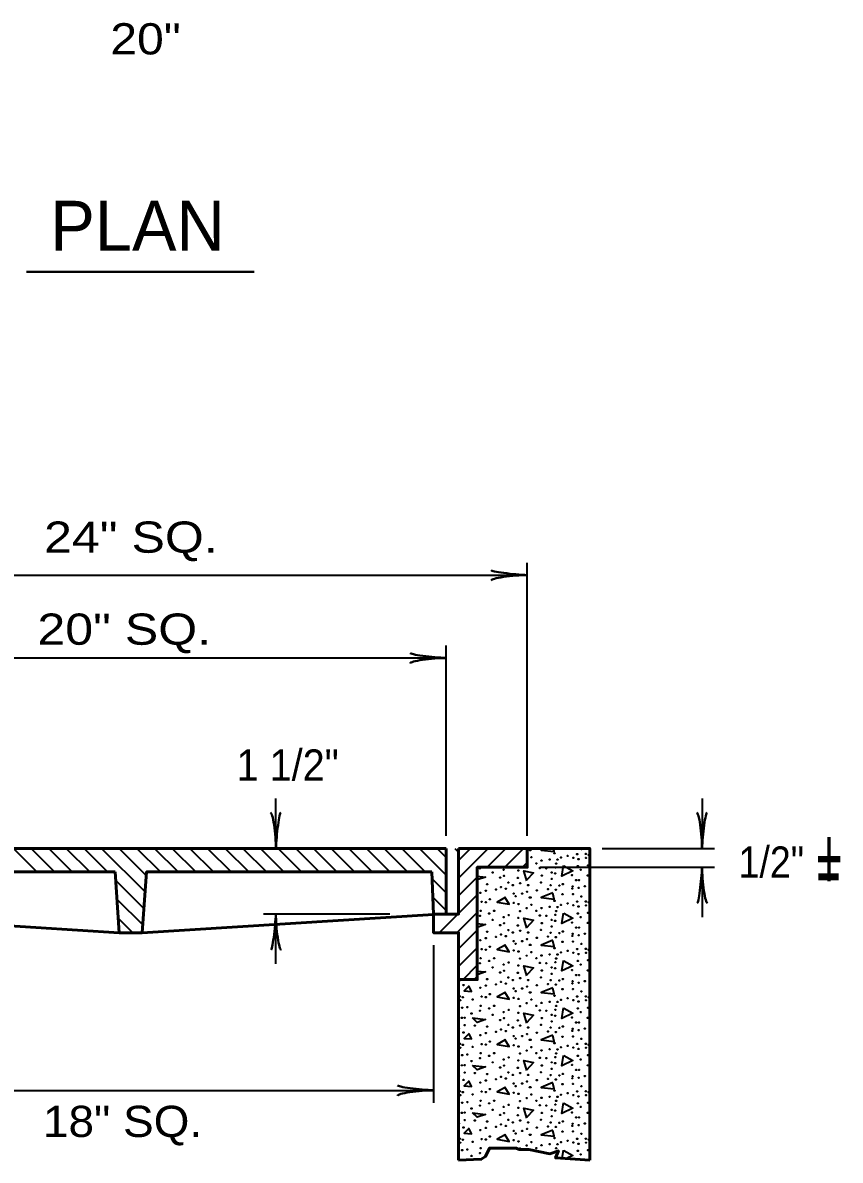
# Model space of a CAD drawing. Extents: x 788 to 1469, y -1 to 439.
# Drawn here: x 1143.7 to 1209.2, y 217.4 to 308.5 of the extents above; entities that cross this region are included whole.
import ezdxf

# ---------------------------------------------------------------- set-up
doc = ezdxf.new("R2010")
doc.units = 0
doc.layers.add('1', color=7, linetype='Continuous', lineweight=35)

msp = doc.modelspace()

# ---------------------------------------------------------------- linework, layer by layer
at = {"layer": '1', "lineweight": 40}
msp.add_line((1144.038, 288.534), (1162.275, 288.534), dxfattribs=at)
at = {"layer": '1'}
for p, q in [((1184.152, 243.348), (1184.152, 265.229)), ((1120.652, 264.229), (1184.152, 264.229)), ((1177.652, 243.348), (1177.652, 258.601)), ((1127.152, 257.601), (1177.652, 257.601)), ((1164.019, 242.348), (1164.019, 246.348)), ((1198.152, 246.348), (1198.152, 242.348)), ((1142.996, 242.348), (1144.871, 240.473)), ((1144.41, 242.348), (1146.285, 240.473)), ((1145.824, 242.348), (1147.699, 240.473)), ((1147.238, 242.348), (1149.113, 240.473)), ((1148.653, 242.348), (1150.528, 240.473)), ((1150.067, 242.348), (1153.55, 238.865)), ((1151.481, 242.348), (1153.641, 240.188)), ((1152.895, 242.348), (1154.77, 240.473)), ((1154.31, 242.348), (1156.185, 240.473)), ((1155.724, 242.348), (1157.599, 240.473)), ((1157.138, 242.348), (1159.013, 240.473)), ((1158.552, 242.348), (1160.427, 240.473)), ((1159.966, 242.348), (1161.841, 240.473)), ((1161.381, 242.348), (1163.256, 240.473)), ((1162.795, 242.348), (1164.67, 240.473)), ((1164.209, 242.348), (1166.084, 240.473)), ((1165.623, 242.348), (1167.498, 240.473)), ((1167.037, 242.348), (1168.912, 240.473)), ((1168.452, 242.348), (1170.327, 240.473)), ((1169.866, 242.348), (1171.741, 240.473)), ((1171.28, 242.348), (1173.155, 240.473)), ((1172.694, 242.348), (1174.569, 240.473)), ((1174.109, 242.348), (1175.984, 240.473)), ((1175.523, 242.348), (1177.652, 240.219)), ((1176.937, 242.348), (1177.652, 241.633)), ((1178.351, 242.348), (1178.652, 242.047)), ((1178.652, 241.388), (1179.612, 242.348)), ((1178.652, 239.973), (1181.026, 242.348)), ((1180.941, 240.848), (1182.441, 242.348)), ((1182.355, 240.848), (1183.855, 242.348)), ((1190.152, 242.348), (1199.152, 242.348)), ((1183.769, 240.848), (1184.152, 241.231)), ((1185.152, 240.848), (1199.152, 240.848)), ((1198.152, 240.848), (1198.152, 236.848)), ((1151.189, 239.812), (1153.458, 237.542)), ((1176.544, 239.913), (1177.652, 238.805)), ((1178.652, 238.559), (1180.152, 240.059)), ((1151.294, 238.293), (1153.367, 236.219)), ((1176.6, 238.442), (1177.652, 237.39)), ((1178.652, 237.145), (1180.152, 238.645)), ((1173.152, 237.098), (1163.019, 237.098)), ((1164.019, 233.098), (1164.019, 237.098)), ((1177.152, 237.059), (1177.191, 237.098)), ((1177.152, 235.645), (1178.605, 237.098)), ((1178.519, 235.598), (1180.152, 237.231)), ((1151.398, 236.774), (1152.574, 235.598)), ((1178.652, 234.317), (1180.152, 235.817)), ((1176.652, 234.598), (1176.652, 221.972)), ((1178.652, 232.902), (1180.152, 234.402)), ((1179.012, 231.848), (1180.152, 232.988)), ((1128.152, 222.972), (1176.652, 222.972)), ((1186.957, 217.531), (1187.049, 218.176))]:
    msp.add_line(p, q, dxfattribs=at)
at = {"layer": '1', "lineweight": 53}
for p, q in [((1127.152, 242.348), (1177.652, 242.348)), ((1177.652, 237.098), (1177.652, 242.348)), ((1178.652, 242.348), (1178.652, 238.598)), ((1151.143, 240.473), (1128.282, 240.473)), ((1176.522, 240.473), (1176.652, 237.079)), ((1128.152, 237.066), (1151.479, 235.598)), ((1153.324, 235.598), (1176.651, 237.066)), ((1180.152, 232.017), (1179.983, 231.848))]:
    msp.add_line(p, q, dxfattribs=at)
msp.add_lwpolyline([(1178.652, 242.348), (1184.152, 242.348), (1184.152, 240.848), (1180.152, 240.848), (1180.152, 231.848), (1178.652, 231.848), (1178.652, 235.598), (1176.651, 235.598), (1176.651, 237.098), (1178.652, 237.098)], close=True, dxfattribs=at)
for points in [[(1189.152, 217.379), (1189.152, 242.348), (1184.152, 242.348), (1184.152, 240.848), (1180.152, 240.848), (1180.152, 231.848), (1178.652, 231.848), (1178.652, 217.379)], [(1176.522, 240.473), (1153.66, 240.473), (1153.324, 235.598), (1151.479, 235.598), (1151.143, 240.473)], [(1178.652, 217.379), (1180.461, 217.456), (1180.799, 217.681), (1181.136, 218.356), (1183.271, 218.356), (1183.496, 218.243), (1184.283, 218.243), (1185.969, 217.906), (1186.643, 218.131), (1186.419, 217.569), (1189.152, 217.379)]]:
    msp.add_lwpolyline(points, dxfattribs=at)
at = {"layer": '1'}
for points in [[(1185.595, 242.348), (1185.269, 242.216), (1186.31, 242.096), (1186.255, 242.348)], [(1184.11, 239.756), (1183.87, 240.556), (1184.649, 240.396), (1184.09, 239.796)], [(1187.09, 240.956), (1187.789, 240.556), (1186.929, 240.136), (1187.049, 240.976)], [(1180.152, 240.132), (1180.81, 240.056), (1180.152, 239.824)], [(1186.209, 238.796), (1185.269, 238.416), (1186.31, 238.296), (1186.209, 238.756)], [(1182.389, 238.416), (1181.729, 238.056), (1182.709, 237.876), (1182.35, 238.436)], [(1187.09, 237.156), (1187.789, 236.756), (1186.929, 236.336), (1187.049, 237.176)], [(1180.152, 236.332), (1180.81, 236.256), (1180.152, 236.024)], [(1184.11, 235.956), (1183.87, 236.756), (1184.649, 236.596), (1184.09, 235.996)], [(1182.389, 234.616), (1181.729, 234.256), (1182.709, 234.076), (1182.35, 234.636)], [(1186.209, 234.996), (1185.269, 234.616), (1186.31, 234.496), (1186.209, 234.956)], [(1187.09, 233.356), (1187.789, 232.956), (1186.929, 232.536), (1187.049, 233.376)], [(1180.152, 232.532), (1180.81, 232.456), (1180.152, 232.224)], [(1184.11, 232.156), (1183.87, 232.956), (1184.649, 232.796), (1184.09, 232.196)], [(1179.489, 231.336), (1179.11, 230.936), (1179.689, 230.896), (1179.489, 231.296)], [(1182.389, 230.816), (1181.729, 230.456), (1182.709, 230.276), (1182.35, 230.836)], [(1186.209, 231.196), (1185.269, 230.816), (1186.31, 230.696), (1186.209, 231.156)], [(1187.09, 229.556), (1187.789, 229.156), (1186.929, 228.736), (1187.049, 229.576)], [(1184.11, 228.356), (1183.87, 229.156), (1184.649, 228.996), (1184.09, 228.396)], [(1179.489, 227.536), (1179.11, 227.136), (1179.689, 227.096), (1179.489, 227.496)], [(1182.389, 227.016), (1181.729, 226.656), (1182.709, 226.476), (1182.35, 227.036)], [(1186.209, 227.396), (1185.269, 227.016), (1186.31, 226.896), (1186.209, 227.356)], [(1184.11, 224.556), (1183.87, 225.356), (1184.649, 225.196), (1184.09, 224.596)], [(1187.09, 225.756), (1187.789, 225.356), (1186.929, 224.936), (1187.049, 225.776)], [(1179.489, 223.736), (1179.11, 223.336), (1179.689, 223.296), (1179.489, 223.696)], [(1182.389, 223.216), (1181.729, 222.856), (1182.709, 222.676), (1182.35, 223.236)], [(1186.209, 223.596), (1185.269, 223.216), (1186.31, 223.096), (1186.209, 223.556)], [(1184.11, 220.756), (1183.87, 221.556), (1184.649, 221.396), (1184.09, 220.796)], [(1187.09, 221.956), (1187.789, 221.556), (1186.929, 221.136), (1187.049, 221.976)], [(1179.489, 219.936), (1179.11, 219.536), (1179.689, 219.496), (1179.489, 219.896)], [(1186.209, 219.796), (1185.269, 219.416), (1186.31, 219.296), (1186.209, 219.756)], [(1182.389, 219.416), (1181.729, 219.056), (1182.709, 218.876), (1182.35, 219.436)], [(1187.09, 218.156), (1187.789, 217.756), (1187.283, 217.509)]]:
    msp.add_lwpolyline(points, dxfattribs=at)
for points in [[(1179.769, 228.776), (1180.81, 228.656), (1180.13, 228.416)], [(1179.769, 224.976), (1180.81, 224.856), (1180.13, 224.616)], [(1179.769, 221.176), (1180.81, 221.056), (1180.13, 220.816)]]:
    msp.add_lwpolyline(points, close=True, dxfattribs=at)
for centre in [(1188.485, 242.303), (1184.363, 242.223), (1184.416, 242.223), (1184.482, 241.64), (1185.291, 241.375), (1185.94, 241.468), (1186.338, 241.958), (1186.576, 241.454), (1186.854, 241.627), (1187.385, 241.746), (1187.835, 241.6), (1188.153, 241.892), (1188.259, 241.494), (1188.843, 241.905), (1188.856, 241.587), (1189.075, 241.826), (1180.361, 240.752), (1182.256, 240.646), (1182.666, 240.818), (1183.435, 240.579), (1184.88, 241.15), (1185.158, 240.778), (1185.675, 240.752), (1186.404, 240.831), (1186.47, 241.136), (1188.206, 240.937), (1188.432, 240.646), (1189.015, 240.99), (1181.381, 240.42), (1181.977, 240.009), (1182.295, 240.155), (1182.64, 239.612), (1183.395, 239.983), (1183.581, 239.559), (1185.251, 239.625), (1185.317, 240.169), (1186.099, 240.42), (1186.112, 239.903), (1186.391, 240.354), (1187.742, 240.208), (1188.074, 239.811), (1188.299, 239.811), (1188.995, 240.18), (1180.387, 238.795), (1180.838, 238.967), (1180.944, 239.479), (1181.646, 239.06), (1182.044, 239.254), (1182.441, 239.126), (1182.998, 239.413), (1183.064, 238.728), (1183.74, 238.728), (1184.138, 238.887), (1184.23, 239.413), (1184.92, 238.993), (1185.808, 239.086), (1186.02, 239.4), (1186.444, 239.046), (1186.722, 239.373), (1186.974, 238.675), (1187, 239.492), (1187.769, 239.139), (1187.782, 239.307), (1187.809, 238.689), (1188.273, 239.192), (1188.763, 239.32), (1180.493, 238.079), (1180.838, 238.039), (1181.156, 238.278), (1183.064, 237.986), (1183.223, 238.516), (1183.448, 237.893), (1184.363, 238.423), (1184.416, 238.423), (1184.482, 237.84), (1186.338, 238.158), (1186.854, 237.827), (1187.385, 237.946), (1187.835, 237.8), (1188.153, 238.092), (1188.485, 238.503), (1188.843, 238.105), (1188.856, 237.787), (1189.075, 238.026), (1180.361, 236.952), (1180.413, 237.35), (1181.103, 237.137), (1181.5, 237.35), (1182.256, 236.846), (1182.666, 237.018), (1183.568, 237.323), (1184.111, 237.562), (1184.88, 237.35), (1185.158, 236.978), (1185.291, 237.575), (1185.675, 236.952), (1185.94, 237.668), (1186.404, 237.031), (1186.47, 237.336), (1186.576, 237.654), (1188.206, 237.137), (1188.259, 237.694), (1188.432, 236.846), (1189.015, 237.19), (1181.381, 236.62), (1181.977, 236.209), (1182.295, 236.355), (1183.395, 236.183), (1183.435, 236.779), (1185.317, 236.369), (1186.099, 236.62), (1186.112, 236.103), (1186.391, 236.554), (1187.742, 236.408), (1188.074, 236.011), (1188.299, 236.011), (1188.995, 236.38), (1180.387, 234.995), (1180.838, 235.167), (1180.944, 235.679), (1181.646, 235.26), (1182.044, 235.454), (1182.441, 235.326), (1182.64, 235.812), (1182.998, 235.613), (1183.581, 235.759), (1184.138, 235.087), (1184.23, 235.613), (1184.92, 235.193), (1185.251, 235.825), (1185.808, 235.286), (1186.02, 235.6), (1186.444, 235.246), (1186.722, 235.573), (1187, 235.692), (1187.769, 235.339), (1187.782, 235.507), (1188.273, 235.392), (1188.763, 235.52), (1180.493, 234.279), (1180.838, 234.239), (1181.156, 234.478), (1183.064, 234.928), (1183.064, 234.186), (1183.223, 234.716), (1183.448, 234.093), (1183.74, 234.928), (1184.363, 234.623), (1184.416, 234.623), (1186.338, 234.358), (1186.974, 234.875), (1187.385, 234.146), (1187.809, 234.889), (1188.153, 234.292), (1188.485, 234.703), (1188.843, 234.305), (1189.075, 234.226), (1180.413, 233.55), (1181.103, 233.337), (1181.5, 233.55), (1182.666, 233.218), (1183.568, 233.523), (1184.111, 233.762), (1184.482, 234.04), (1184.88, 233.55), (1185.158, 233.178), (1185.291, 233.775), (1185.94, 233.868), (1186.404, 233.231), (1186.47, 233.536), (1186.576, 233.854), (1186.854, 234.027), (1187.835, 234), (1188.206, 233.337), (1188.259, 233.894), (1188.856, 233.987), (1189.015, 233.39), (1180.361, 233.152), (1181.381, 232.82), (1181.977, 232.409), (1182.256, 233.046), (1182.295, 232.555), (1183.395, 232.383), (1183.435, 232.979), (1185.317, 232.569), (1185.675, 233.152), (1186.099, 232.82), (1186.112, 232.303), (1186.391, 232.754), (1187.742, 232.608), (1188.432, 233.046), (1188.995, 232.58), (1178.683, 231.72), (1179.048, 231.407), (1180.838, 231.367), (1180.944, 231.879), (1181.646, 231.46), (1182.044, 231.654), (1182.441, 231.526), (1182.64, 232.012), (1182.998, 231.813), (1183.581, 231.959), (1184.23, 231.813), (1184.92, 231.393), (1185.251, 232.025), (1185.808, 231.486), (1186.02, 231.8), (1186.444, 231.446), (1186.722, 231.773), (1187, 231.892), (1187.769, 231.539), (1187.782, 231.707), (1188.074, 232.211), (1188.273, 231.592), (1188.299, 232.211), (1188.763, 231.72), (1178.763, 230.505), (1180.387, 231.195), (1180.493, 230.479), (1180.838, 230.439), (1181.156, 230.678), (1183.064, 231.128), (1183.223, 230.916), (1183.74, 231.128), (1184.138, 231.287), (1184.363, 230.823), (1184.416, 230.823), (1186.338, 230.558), (1186.974, 231.075), (1187.809, 231.089), (1188.153, 230.492), (1188.485, 230.903), (1188.843, 230.505), (1178.776, 230.187), (1178.935, 229.59), (1178.995, 230.426), (1179.353, 229.643), (1179.777, 230.253), (1180.413, 229.75), (1181.103, 229.537), (1181.5, 229.75), (1183.064, 230.386), (1183.448, 230.293), (1183.568, 229.723), (1184.111, 229.962), (1184.482, 230.24), (1184.88, 229.75), (1185.291, 229.975), (1185.94, 230.068), (1186.47, 229.736), (1186.576, 230.054), (1186.854, 230.227), (1187.385, 230.346), (1187.835, 230.2), (1188.206, 229.537), (1188.259, 230.094), (1188.856, 230.187), (1189.015, 229.59), (1189.075, 230.426), (1178.915, 228.78), (1179.141, 228.795), (1179.685, 229.126), (1180.361, 229.352), (1181.381, 229.02), (1182.256, 229.246), (1182.295, 228.755), (1182.666, 229.418), (1183.435, 229.179), (1185.158, 229.378), (1185.317, 228.769), (1185.675, 229.352), (1186.099, 229.02), (1186.391, 228.954), (1186.404, 229.431), (1187.742, 228.808), (1188.432, 229.246), (1188.995, 228.78), (1178.683, 227.92), (1179.141, 228.198), (1179.95, 228.159), (1180.944, 228.079), (1181.977, 228.609), (1182.044, 227.854), (1182.441, 227.726), (1182.64, 228.212), (1182.998, 228.013), (1183.395, 228.583), (1183.581, 228.159), (1184.23, 228.013), (1185.251, 228.225), (1186.02, 228), (1186.112, 228.503), (1186.722, 227.973), (1187, 228.092), (1187.769, 227.739), (1187.782, 227.907), (1188.074, 228.411), (1188.273, 227.792), (1188.299, 228.411), (1188.763, 227.92), (1179.048, 227.607), (1180.387, 227.395), (1180.838, 227.567), (1181.156, 226.878), (1181.646, 227.66), (1183.064, 227.328), (1183.223, 227.116), (1183.74, 227.328), (1184.138, 227.487), (1184.363, 227.023), (1184.416, 227.023), (1184.92, 227.593), (1185.808, 227.686), (1186.444, 227.646), (1186.974, 227.275), (1187.809, 227.289), (1188.485, 227.103), (1178.763, 226.705), (1178.776, 226.387), (1178.995, 226.626), (1179.777, 226.453), (1180.413, 225.95), (1180.493, 226.679), (1180.838, 226.639), (1181.5, 225.95), (1183.064, 226.586), (1183.448, 226.493), (1183.568, 225.923), (1184.111, 226.162), (1184.482, 226.44), (1184.88, 225.95), (1185.291, 226.175), (1185.94, 226.268), (1186.338, 226.758), (1186.47, 225.936), (1186.576, 226.254), (1186.854, 226.427), (1187.385, 226.546), (1187.835, 226.4), (1188.153, 226.692), (1188.259, 226.294), (1188.843, 226.705), (1188.856, 226.387), (1189.075, 226.626), (1178.915, 224.98), (1178.935, 225.79), (1179.141, 224.995), (1179.353, 225.843), (1179.685, 225.326), (1180.361, 225.552), (1181.103, 225.737), (1181.381, 225.22), (1182.256, 225.446), (1182.666, 225.618), (1183.435, 225.379), (1185.158, 225.578), (1185.317, 224.969), (1185.675, 225.552), (1186.099, 225.22), (1186.391, 225.154), (1186.404, 225.631), (1187.742, 225.008), (1188.206, 225.737), (1188.432, 225.446), (1188.995, 224.98), (1189.015, 225.79), (1178.683, 224.12), (1179.141, 224.398), (1179.95, 224.359), (1180.944, 224.279), (1181.977, 224.809), (1182.295, 224.955), (1182.64, 224.412), (1182.998, 224.213), (1183.395, 224.783), (1183.581, 224.359), (1184.23, 224.213), (1185.251, 224.425), (1186.02, 224.2), (1186.112, 224.703), (1186.722, 224.173), (1187, 224.292), (1187.782, 224.107), (1188.074, 224.611), (1188.299, 224.611), (1188.763, 224.12), (1179.048, 223.807), (1180.387, 223.595), (1180.838, 223.767), (1181.646, 223.86), (1182.044, 224.054), (1182.441, 223.926), (1183.064, 223.528), (1183.223, 223.316), (1183.74, 223.528), (1184.138, 223.687), (1184.363, 223.223), (1184.416, 223.223), (1184.92, 223.793), (1185.808, 223.886), (1186.444, 223.846), (1186.974, 223.475), (1187.769, 223.939), (1187.809, 223.489), (1188.273, 223.992), (1188.485, 223.303), (1178.763, 222.905), (1178.776, 222.587), (1178.995, 222.826), (1179.777, 222.653), (1180.493, 222.879), (1180.838, 222.839), (1181.156, 223.078), (1183.064, 222.786), (1183.448, 222.693), (1184.111, 222.362), (1184.482, 222.64), (1185.291, 222.375), (1185.94, 222.468), (1186.338, 222.958), (1186.576, 222.454), (1186.854, 222.627), (1187.385, 222.746), (1187.835, 222.6), (1188.153, 222.892), (1188.259, 222.494), (1188.843, 222.905), (1188.856, 222.587), (1189.075, 222.826), (1178.935, 221.99), (1179.353, 222.043), (1179.685, 221.526), (1180.361, 221.752), (1180.413, 222.15), (1181.103, 221.937), (1181.381, 221.42), (1181.5, 222.15), (1182.256, 221.646), (1182.666, 221.818), (1183.435, 221.579), (1183.568, 222.123), (1184.88, 222.15), (1185.158, 221.778), (1185.675, 221.752), (1186.099, 221.42), (1186.391, 221.354), (1186.404, 221.831), (1186.47, 222.136), (1188.206, 221.937), (1188.432, 221.646), (1189.015, 221.99), (1178.915, 221.18), (1179.141, 221.195), (1179.141, 220.598), (1179.95, 220.559), (1180.944, 220.479), (1181.977, 221.009), (1182.295, 221.155), (1182.64, 220.612), (1183.395, 220.983), (1183.581, 220.559), (1185.251, 220.625), (1185.317, 221.169), (1186.112, 220.903), (1187, 220.492), (1187.742, 221.208), (1188.074, 220.811), (1188.299, 220.811), (1188.995, 221.18), (1178.683, 220.32), (1179.048, 220.007), (1180.387, 219.795), (1180.838, 219.967), (1181.646, 220.06), (1182.044, 220.254), (1182.441, 220.126), (1182.998, 220.413), (1183.064, 219.728), (1183.223, 219.516), (1183.74, 219.728), (1184.138, 219.887), (1184.23, 220.413), (1184.92, 219.993), (1185.808, 220.086), (1186.02, 220.4), (1186.444, 220.046), (1186.722, 220.373), (1186.974, 219.675), (1187.769, 220.139), (1187.782, 220.307), (1187.809, 219.689), (1188.273, 220.192), (1188.763, 220.32), (1178.763, 219.105), (1178.776, 218.787), (1178.995, 219.026), (1179.777, 218.853), (1180.493, 219.079), (1180.838, 219.039), (1181.156, 219.278), (1183.064, 218.986), (1183.448, 218.893), (1184.363, 219.423), (1184.416, 219.423), (1184.482, 218.84), (1185.94, 218.668), (1186.338, 219.158), (1186.576, 218.654), (1186.854, 218.827), (1187.385, 218.946), (1187.835, 218.8), (1188.153, 219.092), (1188.259, 218.694), (1188.485, 219.503), (1188.843, 219.105), (1188.856, 218.787), (1189.075, 219.026), (1178.935, 218.19), (1179.353, 218.243), (1179.685, 217.726), (1180.361, 217.952), (1180.413, 218.35), (1183.568, 218.323), (1184.111, 218.562), (1184.88, 218.35), (1185.291, 218.575), (1186.47, 218.336), (1188.206, 218.137), (1188.432, 217.846), (1189.015, 218.19)]:
    msp.add_circle(centre, 0.0265, dxfattribs=at)
for centre, start, end in [((1189.128, 239.007), 27.85843, 332.14157), ((1189.128, 235.207), 27.85843, 332.14157), ((1189.128, 231.407), 27.85843, 332.14157), ((1189.128, 227.607), 27.85843, 332.14157), ((1189.128, 223.807), 27.85843, 332.14157), ((1189.128, 220.007), 27.85843, 332.14157), ((1181.5, 218.35), 13.13607, 166.86393), ((1185.675, 217.952), 17.06003, 140.31684), ((1186.404, 218.031), 62.62244, 154.2517), ((1178.915, 217.38), 27.03956, 157.81244), ((1179.141, 217.395), 13.46436, 171.38764), ((1188.995, 217.38), 19.89382, 152.19147)]:
    msp.add_arc(centre, 0.0265, start, end, dxfattribs=at)
at = {"layer": '1', "lineweight": 40}
for centre, major_axis, ratio, start_param, end_param in [((1183.052, 263.961), (1.786, 0.156), 0.122415, 0.896353, 3.141593), ((1183.022, 264.449), (1.756, -0.176), 0.07063, 3.140715, 5.41811), ((1176.531, 257.813), (1.756, -0.176), 0.07063, 3.140715, 5.41811), ((1176.561, 257.325), (1.786, 0.156), 0.122415, 0.896353, 3.141593), ((1163.742, 243.439), (0.156, -1.786), 0.122415, 0.896353, 3.141593), ((1164.23, 243.469), (-0.176, -1.756), 0.07063, 3.140715, 5.41811), ((1197.876, 243.439), (0.156, -1.786), 0.122415, 0.896353, 3.141593), ((1197.876, 243.439), (0.156, -1.786), 0.122415, 0.896353, 3.141593), ((1198.363, 243.469), (-0.176, -1.756), 0.07063, 3.140715, 5.41811), ((1198.363, 243.469), (-0.176, -1.756), 0.07063, 3.140715, 5.41811), ((1197.94, 239.727), (0.176, 1.756), 0.07063, 3.140715, 5.41811), ((1197.94, 239.727), (0.176, 1.756), 0.07063, 3.140715, 5.41811), ((1198.428, 239.757), (-0.156, 1.786), 0.122415, 0.896353, 3.141593), ((1198.428, 239.757), (-0.156, 1.786), 0.122415, 0.896353, 3.141593), ((1163.807, 235.977), (0.176, 1.756), 0.07063, 3.140715, 5.41811), ((1164.295, 236.007), (-0.156, 1.786), 0.122415, 0.896353, 3.141593), ((1175.522, 223.192), (1.756, -0.176), 0.07063, 3.140715, 5.41811), ((1175.552, 222.704), (1.786, 0.156), 0.122415, 0.896353, 3.141593)]:
    msp.add_ellipse(centre, major_axis=major_axis, ratio=ratio, start_param=start_param, end_param=end_param, dxfattribs=at)

# ---------------------------------------------------------------- texts
at = {"layer": '1'}
for s, width, p in [('20"', 1.15, (1150.765, 305.933)), ('24" SQ.', 1.2, (1145.455, 266.029)), ('20" SQ.', 1.2, (1144.921, 258.66)), ('1 1/2"', 0.95, (1160.867, 247.78)), ('1/2"', 0.9, (1201.073, 240.009)), ('18" SQ.', 1.1, (1145.365, 219.242))]:
    msp.add_text(s, height=2.5, dxfattribs=dict(at, width=width)).set_placement(p)
msp.add_text('PLAN', height=4, dxfattribs=at).set_placement((1145.954, 290.211))
at = {"layer": '1', "width": 0.55}
msp.add_text('+', height=5, rotation=180, dxfattribs=at).set_placement((1209.398, 243.909))
at = {"layer": '1'}
msp.add_text('-', height=5, rotation=180, dxfattribs=at).set_placement((1209.398, 242.002))

doc.saveas('drawing.dxf')
